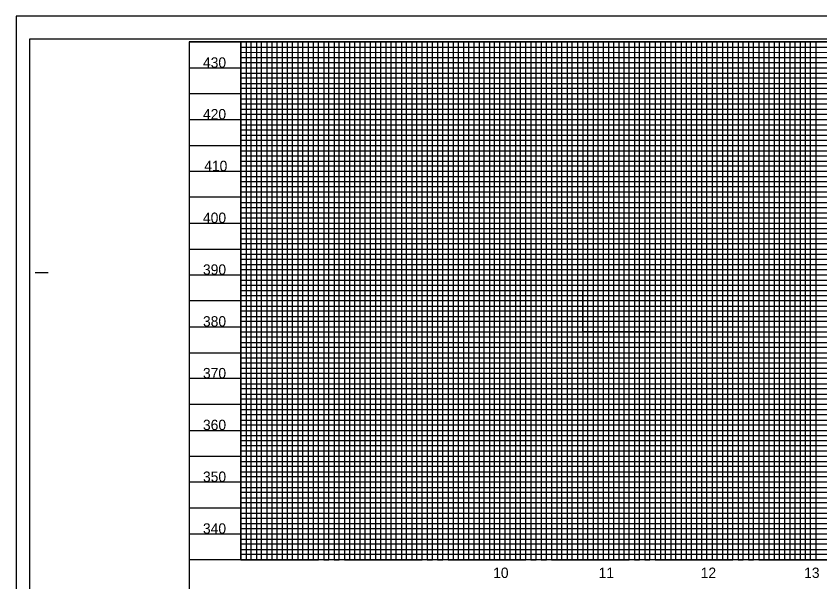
# Model space of a CAD drawing. Extents: x 1629737 to 1631945, y 1172886 to 1173986.
# Drawn here: x 1629737 to 1630513, y 1173440 to 1173986 of the extents above; entities that cross this region are included whole.
import ezdxf

# ---------------------------------------------------------------- set-up
doc = ezdxf.new("R2010")
doc.units = 0
for name, color, linetype in [('Exist Vertical Profile Horizontal Axis Label Major', 7, 'Continuous'), ('Exist Vertical Profile Vertical Axis Label', 7, 'Continuous'), ('Prop Grid Mask', 7, 'Continuous'), ('Sheet Layout Profile Border Port 1', 7, 'Continuous'), ('Sheet Plot Border Inside CELL', 7, 'Continuous'), ('Sheet Plot Border Outside CELL', 7, 'Continuous'), ('Sheet Profile CELL', 7, 'Continuous'), ('Sheet Profile Grid Major CELL', 7, 'Continuous'), ('Sheet Profile Grid Middle CELL', 7, 'Continuous'), ('Sheet Profile Grid Minor CELL', 7, 'Continuous')]:
    doc.layers.add(name, color=color, linetype=linetype)

msp = doc.modelspace()

# ---------------------------------------------------------------- linework, layer by layer
at = {"layer": 'Prop Grid Mask'}
msp.add_lwpolyline([(1630284.31, 1173720.94), (1630354.31, 1173720.94), (1630354.31, 1173680.94), (1630284.31, 1173680.94)], close=True, dxfattribs=at)
at = {"layer": 'Sheet Layout Profile Border Port 1'}
msp.add_lwpolyline([(1629954.31, 1173960.94), (1631004.21, 1173960.94), (1631004.21, 1173934.68), (1631204.26, 1173934.68), (1631204.26, 1173799.89), (1631354.31, 1173799.89), (1631354.31, 1173485.94), (1631154.31, 1173485.94), (1631154.31, 1173460.94), (1630734.31, 1173460.94), (1630734.31, 1173480.94), (1630574.31, 1173480.94), (1630574.31, 1173460.94), (1629954.31, 1173460.94)], close=True, dxfattribs=at)
at = {"layer": 'Sheet Plot Border Inside CELL'}
msp.add_lwpolyline([(1629750.31, 1172908.39), (1631416.81, 1172908.39), (1631416.81, 1173963.49), (1629750.31, 1173963.49)], close=True, dxfattribs=at)
at = {"layer": 'Sheet Plot Border Outside CELL'}
msp.add_lwpolyline([(1629737.31, 1172885.94), (1631421.31, 1172885.94), (1631421.31, 1173985.94), (1629737.31, 1173985.94)], close=True, dxfattribs=at)
at = {"layer": 'Sheet Profile CELL'}
for p, q in [((1629755.81, 1173738.44), (1629768.31, 1173738.44)), ((1631404.31, 1173460.94), (1629904.31, 1173460.94))]:
    msp.add_line(p, q, dxfattribs=at)
msp.add_lwpolyline([(1631404.31, 1173960.94), (1629904.31, 1173960.94), (1629904.31, 1172910.94), (1631404.31, 1172910.94)], close=True, dxfattribs=at)
at = {"layer": 'Sheet Profile Grid Major CELL'}
for p, q in [((1629954.31, 1173960.94), (1629954.31, 1173460.94)), ((1630004.31, 1173460.94), (1630004.31, 1173960.94)), ((1630004.31, 1173960.94), (1630054.31, 1173960.94)), ((1630054.31, 1173960.94), (1630054.31, 1173460.94)), ((1630104.31, 1173460.94), (1630104.31, 1173960.94)), ((1630104.31, 1173960.94), (1630154.31, 1173960.94)), ((1630154.31, 1173960.94), (1630154.31, 1173460.94)), ((1630204.31, 1173460.94), (1630204.31, 1173960.94)), ((1630204.31, 1173960.94), (1630254.31, 1173960.94)), ((1630254.31, 1173960.94), (1630254.31, 1173460.94)), ((1630304.31, 1173460.94), (1630304.31, 1173960.94)), ((1630304.31, 1173960.94), (1630354.31, 1173960.94)), ((1630354.31, 1173960.94), (1630354.31, 1173460.94)), ((1630404.31, 1173460.94), (1630404.31, 1173960.94)), ((1630404.31, 1173960.94), (1630454.31, 1173960.94)), ((1630454.31, 1173960.94), (1630454.31, 1173460.94)), ((1630504.31, 1173460.94), (1630504.31, 1173960.94)), ((1630504.31, 1173960.94), (1630554.31, 1173960.94)), ((1629954.31, 1173460.94), (1630004.31, 1173460.94)), ((1630054.31, 1173460.94), (1630104.31, 1173460.94)), ((1630154.31, 1173460.94), (1630204.31, 1173460.94)), ((1630254.31, 1173460.94), (1630304.31, 1173460.94)), ((1630354.31, 1173460.94), (1630404.31, 1173460.94)), ((1630454.31, 1173460.94), (1630504.31, 1173460.94))]:
    msp.add_line(p, q, dxfattribs=at)
for points in [[(1629904.31, 1173935.94), (1631004.21, 1173935.94)], [(1629904.31, 1173885.94), (1631204.26, 1173885.94)], [(1631204.26, 1173835.94), (1629904.31, 1173835.94), (1629904.31, 1173785.94), (1631404.31, 1173785.94)], [(1631404.31, 1173735.94), (1629904.31, 1173735.94), (1629904.31, 1173685.94), (1631404.31, 1173685.94)], [(1631404.31, 1173635.94), (1629904.31, 1173635.94), (1629904.31, 1173585.94), (1631404.31, 1173585.94)], [(1631404.31, 1173535.94), (1629904.31, 1173535.94), (1629904.31, 1173535.94), (1629904.31, 1173485.94), (1631404.31, 1173485.94)]]:
    msp.add_lwpolyline(points, dxfattribs=at)
at = {"layer": 'Sheet Profile Grid Middle CELL'}
msp.add_line((1629904.31, 1173960.94), (1631004.21, 1173960.94), dxfattribs=at)
for points in [[(1629979.31, 1173960.94), (1629979.31, 1173460.94), (1630029.31, 1173460.94), (1630029.31, 1173960.94), (1630079.31, 1173960.94), (1630079.31, 1173460.94), (1630129.31, 1173460.94), (1630129.31, 1173960.94), (1630179.31, 1173960.94), (1630179.31, 1173460.94), (1630229.31, 1173460.94), (1630229.31, 1173960.94), (1630279.31, 1173960.94), (1630279.31, 1173460.94), (1630329.31, 1173460.94), (1630329.31, 1173960.94), (1630379.31, 1173960.94), (1630379.31, 1173460.94), (1630429.31, 1173460.94), (1630429.31, 1173960.94), (1630479.31, 1173960.94), (1630479.31, 1173460.94), (1630529.31, 1173460.94)], [(1631204.26, 1173910.94), (1629904.31, 1173910.94), (1629904.31, 1173860.94), (1631204.26, 1173860.94)], [(1631204.26, 1173810.94), (1629904.31, 1173810.94), (1629904.31, 1173760.94), (1631404.31, 1173760.94)], [(1631404.31, 1173710.94), (1629904.31, 1173710.94), (1629904.31, 1173660.94), (1631404.31, 1173660.94)], [(1631404.31, 1173610.94), (1629904.31, 1173610.94), (1629904.31, 1173560.94), (1631404.31, 1173560.94)], [(1631404.31, 1173510.94), (1629904.31, 1173510.94)]]:
    msp.add_lwpolyline(points, dxfattribs=at)
at = {"layer": 'Sheet Profile Grid Minor CELL'}
for p, q in [((1630484.31, 1173960.94), (1630484.31, 1173460.94)), ((1630489.31, 1173460.94), (1630489.31, 1173960.94)), ((1630489.31, 1173960.94), (1630494.31, 1173960.94)), ((1630494.31, 1173960.94), (1630494.31, 1173460.94)), ((1630499.31, 1173460.94), (1630499.31, 1173960.94)), ((1630499.31, 1173960.94), (1630509.31, 1173960.94)), ((1630509.31, 1173960.94), (1630509.31, 1173460.94)), ((1629954.31, 1173955.94), (1631004.21, 1173955.94)), ((1629954.31, 1173950.94), (1629954.31, 1173950.94)), ((1631004.21, 1173950.88), (1629954.31, 1173950.59)), ((1629954.31, 1173945.94), (1631004.21, 1173945.94)), ((1631204.31, 1173825.94), (1629954.31, 1173825.94)), ((1631204.31, 1173820.94), (1629954.31, 1173820.94)), ((1631204.31, 1173815.94), (1629954.31, 1173815.94)), ((1629954.31, 1173805.94), (1631204.31, 1173805.94)), ((1631204.31, 1173800.94), (1629954.31, 1173800.94)), ((1629954.31, 1173795.94), (1631354.31, 1173795.94)), ((1631354.31, 1173775.94), (1629954.31, 1173775.94)), ((1629954.31, 1173770.94), (1631354.31, 1173770.94)), ((1631354.31, 1173750.94), (1629954.31, 1173750.94)), ((1629954.31, 1173745.94), (1631354.31, 1173745.94)), ((1631354.31, 1173725.94), (1629954.31, 1173725.94)), ((1629954.31, 1173720.94), (1631354.31, 1173720.94)), ((1631354.31, 1173715.94), (1629954.31, 1173715.94)), ((1629954.31, 1173705.94), (1631354.31, 1173705.94)), ((1631354.31, 1173700.94), (1629954.31, 1173700.94)), ((1629954.31, 1173695.94), (1631354.31, 1173695.94)), ((1631354.31, 1173690.94), (1629954.31, 1173690.94)), ((1629954.31, 1173680.94), (1631354.31, 1173680.94)), ((1631354.31, 1173675.94), (1629954.31, 1173675.94)), ((1629954.31, 1173670.94), (1631354.31, 1173670.94)), ((1631354.31, 1173665.94), (1629954.31, 1173665.94)), ((1629954.31, 1173655.94), (1631354.31, 1173655.94)), ((1631354.31, 1173650.94), (1629954.31, 1173650.94)), ((1629954.31, 1173645.94), (1631354.31, 1173645.94)), ((1631354.31, 1173640.94), (1629954.31, 1173640.94)), ((1629954.31, 1173630.94), (1631354.31, 1173630.94)), ((1631354.31, 1173625.94), (1629954.31, 1173625.94)), ((1629954.31, 1173620.94), (1631354.31, 1173620.94)), ((1631354.31, 1173615.94), (1629954.31, 1173615.94)), ((1629954.31, 1173605.94), (1631354.31, 1173605.94)), ((1631354.31, 1173600.94), (1629954.31, 1173600.94)), ((1629954.31, 1173595.94), (1631354.31, 1173595.94)), ((1631354.31, 1173590.94), (1629954.31, 1173590.94)), ((1629954.31, 1173580.94), (1631354.31, 1173580.94)), ((1631354.31, 1173575.94), (1629954.31, 1173575.94)), ((1631354.31, 1173570.94), (1629954.31, 1173570.94)), ((1631354.31, 1173565.94), (1629954.31, 1173565.94)), ((1629954.31, 1173555.94), (1631354.31, 1173555.94)), ((1631354.31, 1173550.94), (1629954.31, 1173550.94)), ((1629954.31, 1173545.94), (1631354.31, 1173545.94)), ((1631354.31, 1173540.94), (1629954.31, 1173540.94)), ((1629954.31, 1173530.94), (1631354.31, 1173530.94)), ((1631354.31, 1173525.94), (1629954.31, 1173525.94)), ((1629954.31, 1173520.94), (1631354.31, 1173520.94)), ((1631354.31, 1173515.94), (1629954.31, 1173515.94)), ((1629954.31, 1173505.94), (1631354.31, 1173505.94)), ((1631354.31, 1173500.94), (1629954.31, 1173500.94)), ((1629954.31, 1173495.94), (1631354.31, 1173495.94)), ((1631354.31, 1173490.94), (1629954.31, 1173490.94)), ((1629954.31, 1173480.94), (1631154.31, 1173480.94)), ((1630574.31, 1173475.94), (1629954.31, 1173475.94)), ((1629954.31, 1173470.94), (1630574.31, 1173470.94)), ((1630484.31, 1173460.94), (1630489.31, 1173460.94)), ((1630494.31, 1173460.94), (1630499.31, 1173460.94)), ((1630509.31, 1173460.94), (1630514.31, 1173460.94))]:
    msp.add_line(p, q, dxfattribs=at)
for points in [[(1629959.31, 1173960.94), (1629959.31, 1173460.94), (1629964.31, 1173460.94), (1629964.31, 1173960.94), (1629969.31, 1173960.94), (1629969.31, 1173460.94), (1629974.31, 1173460.94), (1629974.31, 1173960.94), (1629984.31, 1173960.94), (1629984.31, 1173460.94), (1629989.31, 1173460.94), (1629989.31, 1173960.94), (1629994.31, 1173960.94), (1629994.31, 1173460.94), (1629999.31, 1173460.94), (1630009.31, 1173460.94), (1630014.31, 1173460.94), (1630014.31, 1173960.94), (1630019.31, 1173960.94), (1630019.31, 1173460.94), (1630024.31, 1173460.94), (1630024.31, 1173960.94), (1630034.31, 1173960.94), (1630034.31, 1173460.94), (1630039.31, 1173460.94), (1630039.31, 1173960.94), (1630044.31, 1173960.94), (1630044.31, 1173460.94), (1630049.31, 1173460.94), (1630049.31, 1173960.94), (1630059.31, 1173960.94), (1630059.31, 1173460.94), (1630064.31, 1173460.94), (1630064.31, 1173960.94), (1630069.31, 1173960.94), (1630069.31, 1173460.94), (1630074.31, 1173460.94), (1630074.31, 1173960.94), (1630084.31, 1173960.94), (1630084.31, 1173460.94), (1630089.31, 1173460.94), (1630089.31, 1173960.94), (1630094.31, 1173960.94), (1630094.31, 1173460.94), (1630099.31, 1173460.94), (1630099.31, 1173960.94), (1630109.31, 1173960.94), (1630109.31, 1173460.94), (1630114.31, 1173460.94), (1630114.31, 1173960.94), (1630119.31, 1173960.94), (1630119.31, 1173460.94), (1630124.31, 1173460.94), (1630124.31, 1173960.94), (1630134.31, 1173960.94), (1630134.31, 1173460.94), (1630139.31, 1173460.94), (1630139.31, 1173960.94), (1630144.31, 1173960.94), (1630144.31, 1173460.94), (1630149.31, 1173460.94), (1630149.31, 1173960.94), (1630159.31, 1173960.94), (1630159.31, 1173460.94), (1630164.31, 1173460.94), (1630164.31, 1173960.94), (1630169.31, 1173960.94), (1630169.31, 1173460.94)], [(1629999.31, 1173460.94), (1629999.31, 1173960.94), (1630009.31, 1173960.94), (1630009.31, 1173460.94)], [(1630169.31, 1173460.94), (1630174.31, 1173460.94), (1630174.31, 1173960.94), (1630184.31, 1173960.94), (1630184.31, 1173460.94), (1630189.31, 1173460.94), (1630189.31, 1173960.94), (1630194.31, 1173960.94), (1630194.31, 1173460.94), (1630199.31, 1173460.94), (1630199.31, 1173960.94), (1630209.31, 1173960.94), (1630209.31, 1173460.94), (1630214.31, 1173460.94), (1630214.31, 1173960.94), (1630219.31, 1173960.94), (1630219.31, 1173460.94), (1630224.31, 1173460.94), (1630224.31, 1173960.94), (1630234.31, 1173960.94), (1630234.31, 1173460.94), (1630239.31, 1173460.94), (1630239.31, 1173960.94), (1630244.31, 1173960.94), (1630244.31, 1173460.94), (1630249.31, 1173460.94), (1630249.31, 1173960.94), (1630259.31, 1173960.94), (1630259.31, 1173460.94), (1630264.31, 1173460.94), (1630264.31, 1173960.94), (1630269.31, 1173960.94), (1630269.31, 1173460.94), (1630274.31, 1173460.94), (1630274.31, 1173960.94), (1630284.31, 1173960.94), (1630284.31, 1173460.94), (1630289.31, 1173460.94), (1630289.31, 1173960.94), (1630294.31, 1173960.94), (1630294.31, 1173460.94), (1630299.31, 1173460.94), (1630299.31, 1173960.94), (1630309.31, 1173960.94), (1630309.31, 1173460.94), (1630314.31, 1173460.94), (1630314.31, 1173960.94), (1630319.31, 1173960.94), (1630319.31, 1173460.94), (1630324.31, 1173460.94), (1630324.31, 1173960.94), (1630334.31, 1173960.94), (1630334.31, 1173460.94), (1630339.31, 1173460.94), (1630339.31, 1173960.94), (1630344.31, 1173960.94), (1630344.31, 1173460.94), (1630349.31, 1173460.94), (1630349.31, 1173960.94), (1630359.31, 1173960.94), (1630359.31, 1173460.94), (1630364.31, 1173460.94), (1630364.31, 1173960.94), (1630369.31, 1173960.94), (1630369.31, 1173460.94), (1630374.31, 1173460.94), (1630374.31, 1173960.94), (1630384.31, 1173960.94), (1630384.31, 1173460.94), (1630389.31, 1173460.94), (1630389.31, 1173960.94), (1630394.31, 1173960.94), (1630394.31, 1173460.94), (1630399.31, 1173460.94), (1630399.31, 1173960.94), (1630409.31, 1173960.94), (1630409.31, 1173460.94), (1630414.31, 1173460.94), (1630414.31, 1173960.94), (1630419.31, 1173960.94), (1630419.31, 1173460.94), (1630424.31, 1173460.94), (1630424.31, 1173960.94), (1630434.31, 1173960.94), (1630434.31, 1173460.94), (1630439.31, 1173460.94), (1630439.31, 1173960.94), (1630444.31, 1173960.94), (1630444.31, 1173460.94), (1630449.31, 1173460.94), (1630449.31, 1173960.94), (1630459.31, 1173960.94), (1630459.31, 1173460.94), (1630464.31, 1173460.94), (1630464.31, 1173960.94), (1630469.31, 1173960.94), (1630469.31, 1173460.94), (1630474.31, 1173460.94), (1630474.31, 1173960.94), (1630484.31, 1173960.94)], [(1631004.21, 1173940.94), (1629954.31, 1173940.94), (1629954.31, 1173930.94), (1631204.26, 1173930.94)], [(1631204.26, 1173925.94), (1629954.31, 1173925.94), (1629954.31, 1173920.94), (1631204.26, 1173920.94)], [(1631204.26, 1173915.94), (1629954.31, 1173915.94), (1629954.31, 1173905.94), (1631204.26, 1173905.94)], [(1631204.26, 1173900.94), (1629954.31, 1173900.94), (1629954.31, 1173895.94), (1631204.26, 1173895.94)], [(1631204.26, 1173890.94), (1629954.31, 1173890.94), (1629954.31, 1173880.94), (1631204.26, 1173880.94)], [(1631204.26, 1173875.94), (1629954.31, 1173875.94), (1629954.31, 1173870.94), (1631204.26, 1173870.94)], [(1631204.26, 1173865.94), (1629954.31, 1173865.94), (1629954.31, 1173855.94), (1631204.26, 1173855.94)], [(1631204.26, 1173850.84), (1629954.41, 1173850.84), (1629954.41, 1173845.94), (1631204.26, 1173845.94)], [(1631204.26, 1173840.94), (1629954.31, 1173840.94), (1629954.31, 1173830.94), (1631204.26, 1173830.94)], [(1631354.31, 1173790.94), (1629954.31, 1173790.94), (1629954.31, 1173780.94), (1631354.31, 1173780.94)], [(1631354.31, 1173765.94), (1629954.31, 1173765.94), (1629954.31, 1173755.94), (1631354.31, 1173755.94)], [(1631354.31, 1173740.94), (1629954.31, 1173740.94), (1629954.31, 1173730.94), (1631354.31, 1173730.94)], [(1630574.31, 1173465.94), (1629954.31, 1173465.94)]]:
    msp.add_lwpolyline(points, dxfattribs=at)

# ---------------------------------------------------------------- texts
at = {"layer": 'Exist Vertical Profile Horizontal Axis Label Major'}
for s, p in [('10', (1630197.9, 1173443.44)), ('11', (1630299.74, 1173443.44)), ('12', (1630398.29, 1173443.44)), ('13', (1630498.12, 1173443.44))]:
    msp.add_text(s, height=10, dxfattribs=at).set_placement(p)
at = {"layer": 'Exist Vertical Profile Vertical Axis Label'}
for s, p in [('430', (1629917.75, 1173936.07)), ('420', (1629917.75, 1173886.19)), ('410', (1629918.94, 1173836.19)), ('400', (1629917.75, 1173786.19)), ('390', (1629917.75, 1173736.19)), ('380', (1629917.75, 1173686.19)), ('370', (1629917.75, 1173636.19)), ('360', (1629917.75, 1173586.19)), ('350', (1629917.75, 1173536.19)), ('340', (1629917.75, 1173486.19))]:
    msp.add_text(s, height=10, dxfattribs=at).set_placement(p)

doc.saveas('drawing.dxf')
